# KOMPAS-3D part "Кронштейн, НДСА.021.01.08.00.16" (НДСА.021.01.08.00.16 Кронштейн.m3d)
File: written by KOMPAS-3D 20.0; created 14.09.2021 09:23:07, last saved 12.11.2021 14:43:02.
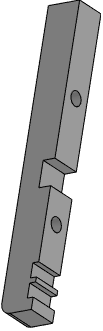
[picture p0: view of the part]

Document properties: Полное имя файла: C:\Users\korychko\Desktop\PLM\НДСА.021.01.08.00.16 Кронштейн.m3d

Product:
- Part/product: Кронштейн  | designation НДСА.021.01.08.00.16
    Материал: Д16  ГОСТ 4784-2019 (density 2800 kg/m3)
    Масса: 0.0741541
    additional columns: <item xmlns="http://appius.ru/pdm" xmlns:xs="http://www.w3.org/2001/XMLSchema" x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; <item xmlns="http://appius.ru/pdm" xmlns:xs="http://www.w3.org/2001/XMLSchema" x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; <item xmlns="http://appius.ru/pdm" xmlns:xs="http://www.w3.org/2001/XMLSchema" x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
    source file: НДСА.021.01.08.00.16 Кронштейн.cdw

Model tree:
1. Эскиз:1
2. Элемент выдавливания:1
     Расстояние 1 = 135
3. Эскиз:2  (with: Элемент выдавливания:1)
4. Элемент выдавливания:2
5. Смещенная плоскость:1
     Расстояние = -5.75
6. Сечение:1
7. Эскиз:3  (with: Элемент выдавливания:1)
8. Элемент выдавливания:3
9. Эскиз:4  (with: Элемент выдавливания:1, Элемент выдавливания:3)
10. Элемент выдавливания:4
     Расстояние 2 = 6
11. Эскиз:5  (with: Элемент выдавливания:1, Сечение:1)
12. Эскиз:6  (with: Элемент выдавливания:1)
13. Элемент выдавливания:6
     Расстояние 2 = 14
14. Отверстие:2  (with: Элемент выдавливания:1, Сечение:1)  (labels: M6)
     Глубина выреза = 15; Диаметр отверстия = 4.91747; Угол конуса дна = 118; Расстояние 1 = 8; Расстояние 2 = 7
15. M6  (with: Элемент выдавливания:1)  (labels: M6; cil0_24705-2004 coarse)
     Длина резьбы = 10; Шаг резьбы = 1; Номинальный диаметр резьбы = 6
16. Скругление:1  (with: Элемент выдавливания:1)  (labels: Д16  ГОСТ 4784-2019)
     Радиус = 5

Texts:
  НДСА.021.01.08.00.16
